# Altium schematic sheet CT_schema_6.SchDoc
size 368 x 245 mm
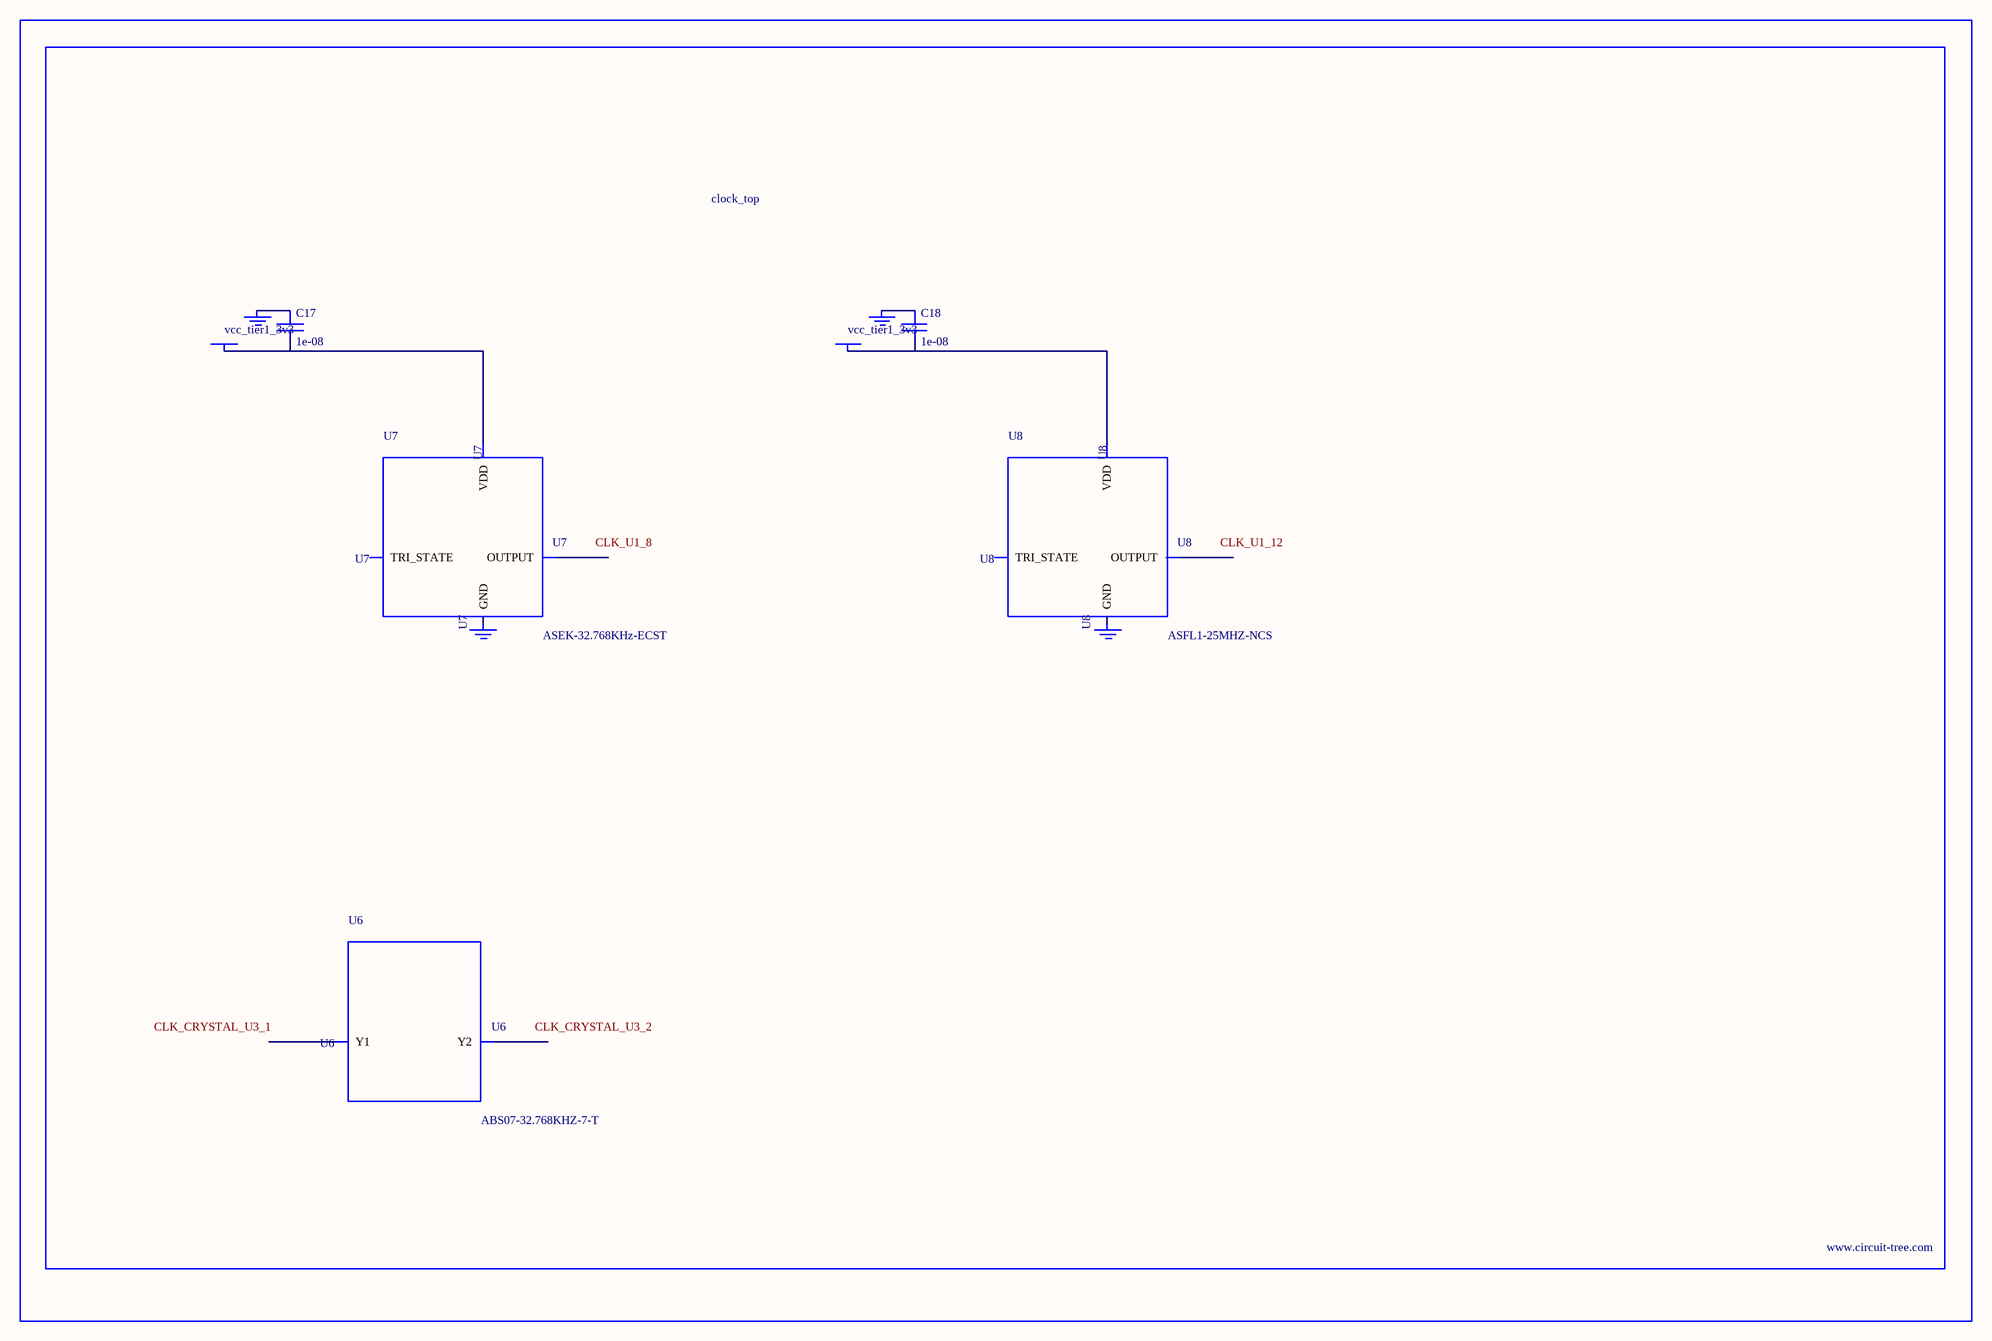
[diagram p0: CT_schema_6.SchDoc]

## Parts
BORDER5  (no value)
C17  1e-08  [C0402]
C18  1e-08  [C0402]
GND_INSTANCE_5_0  (no value)
GND_INSTANCE_5_1  (no value)
GND_INSTANCE_5_2  (no value)
GND_INSTANCE_5_3  (no value)
POWER_INSTANCE_5_0  vcc_tier1_3v3
POWER_INSTANCE_5_1  vcc_tier1_3v3
U6  ABS07-32.768KHZ-7-T  [ABS07-32.768KHZ-7-T]
U7  ASEK-32.768KHz-ECST  [ASEK]
U8  ASFL1-25MHZ-NCS  [ASFL1]

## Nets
NetC17_1: C17.1 GND_INSTANCE_5_0.0(GND)
NetC17_2: C17.2 POWER_INSTANCE_5_0.0(PWR) U7.4(VDD)
NetC18_1: C18.1 GND_INSTANCE_5_2.0(GND)
NetC18_2: C18.2 POWER_INSTANCE_5_1.0(PWR) U8.4(VDD)

Not connected (* = marked no-connect by the designer): GND_INSTANCE_5_1 0(GND); GND_INSTANCE_5_3 0(GND); U6 1(Y1) 2(Y2); U7 1(TRI_STATE) 2(GND) 3(OUTPUT); U8 1(TRI_STATE) 2(GND) 3(OUTPUT)

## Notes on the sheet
- Labels drawn without touching a wire or pin: CLK_CRYSTAL_U3_1, CLK_CRYSTAL_U3_2, CLK_U1_8, CLK_U1_12

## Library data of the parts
BORDER5 = BORDER_PAGE5
C17 C18 = C0402C103K3RAC
GND_INSTANCE_5_0-GND_INSTANCE_5_3 = GND
POWER_INSTANCE_5_0 POWER_INSTANCE_5_1 = PWR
